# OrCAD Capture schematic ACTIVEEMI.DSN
size Custom
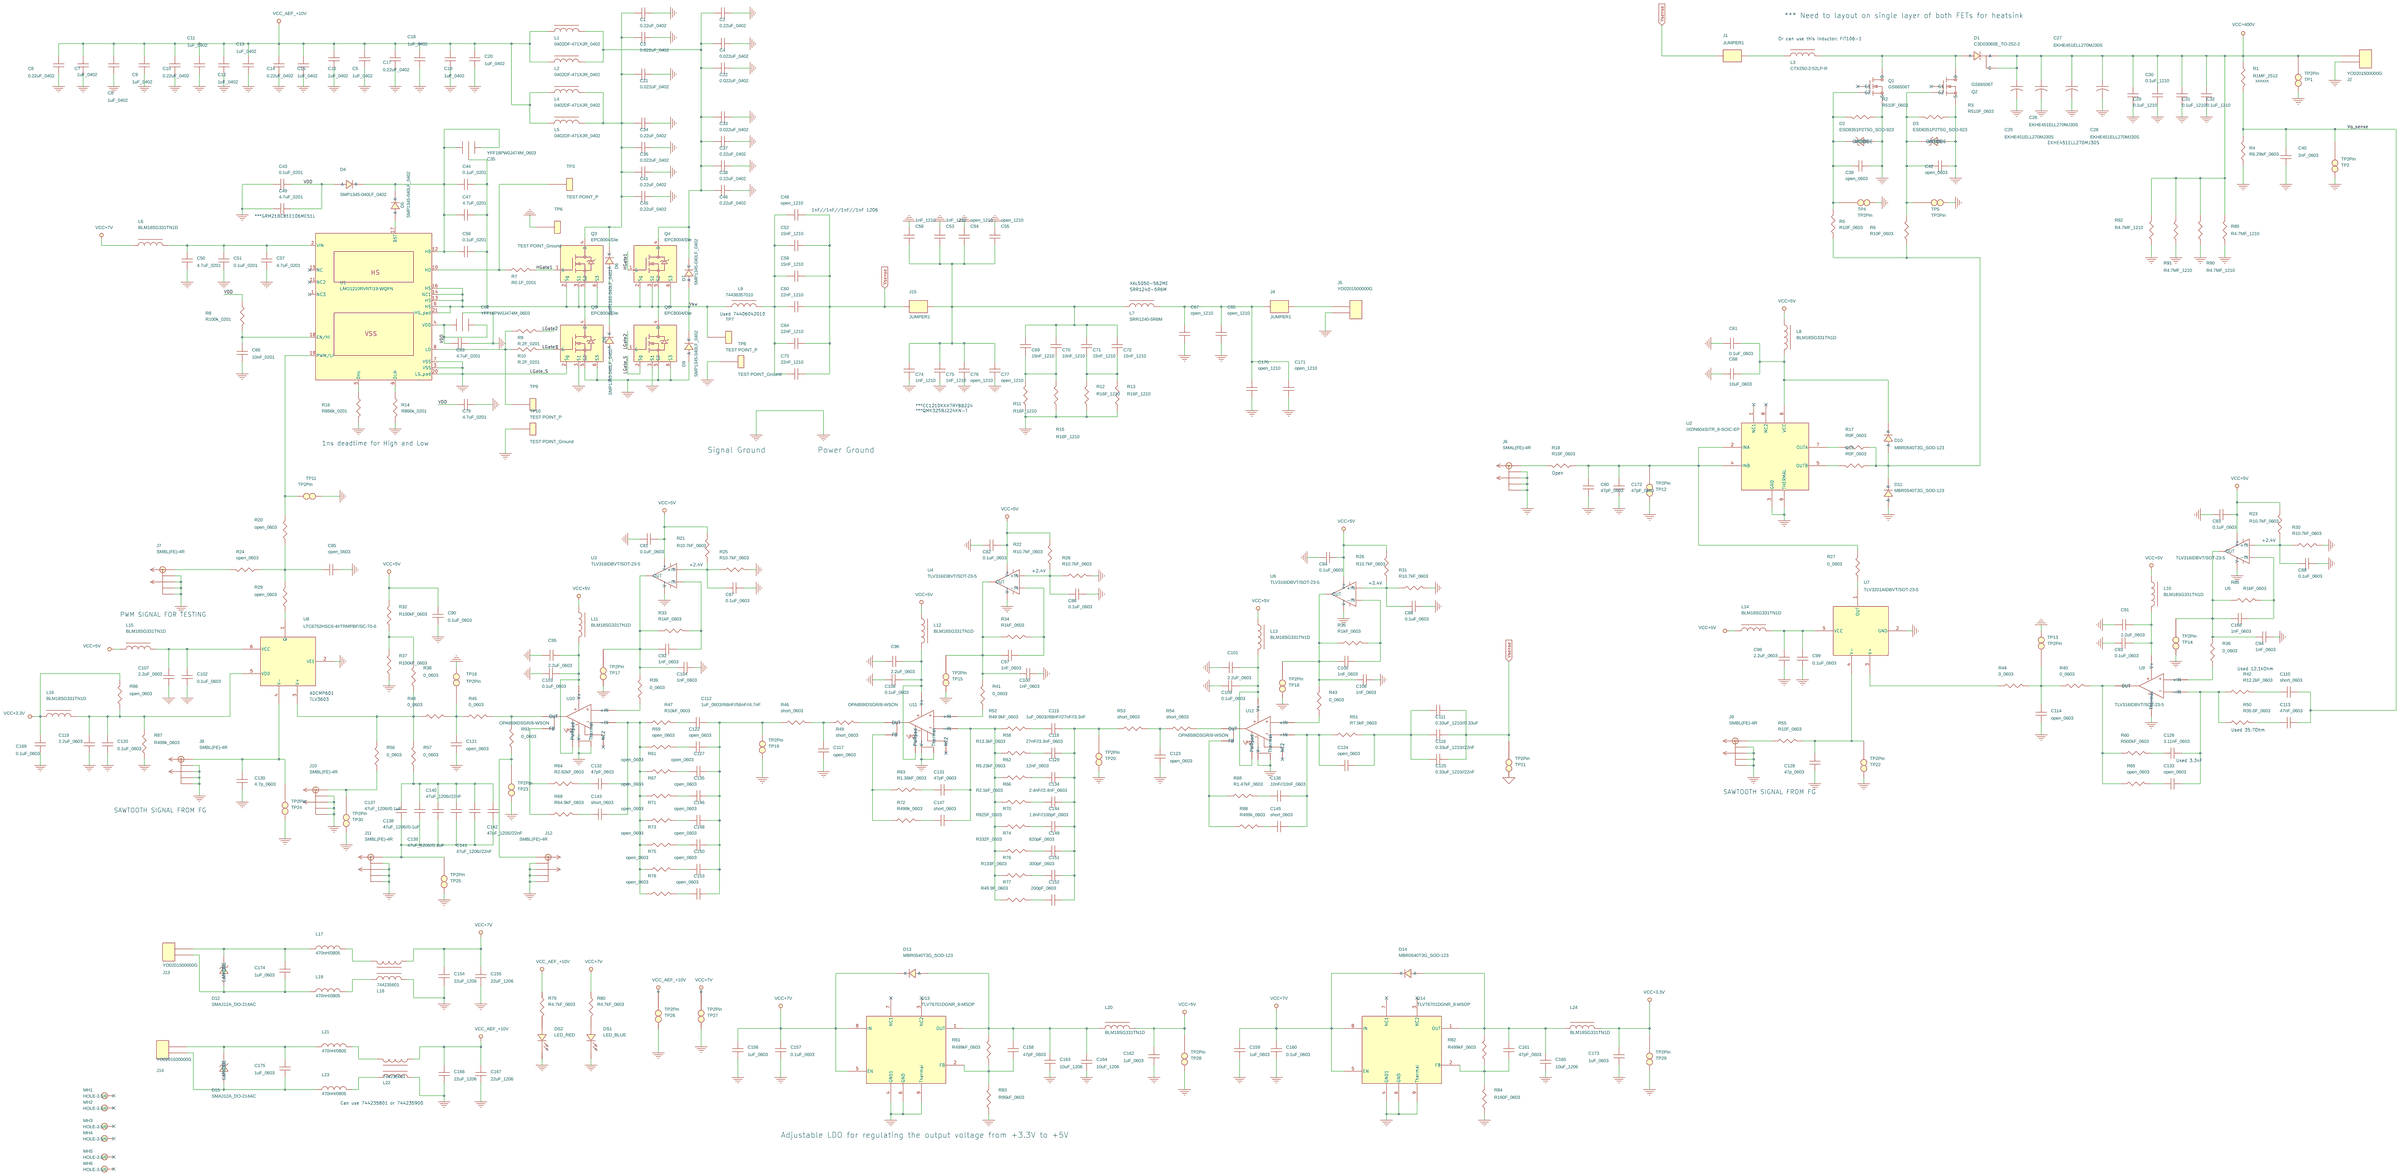
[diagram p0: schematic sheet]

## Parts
C1  0.22uF_0402  [C_0402_SMALL]
C2  0.22uF_0402  [C_0402_SMALL]
C3  0.022uF_0402  [C_0402_SMALL]
C4  0.022uF_0402  [C_0402_SMALL]
C5  1uF_0402  [C_0402_SMALL]
C6  0.22uF_0402  [C_0402_SMALL]
C7  1uF_0402  [C_0402_SMALL]
C8  1uF_0402  [C_0402_SMALL]
C9  1uF_0402  [C_0402_SMALL]
C10  0.22uF_0402  [C_0402_SMALL]
C11  1uF_0402  [C_0402_SMALL]
C12  1uF_0402  [C_0402_SMALL]
C13  1uF_0402  [C_0402_SMALL]
C14  0.22uF_0402  [C_0402_SMALL]
C15  1uF_0402  [C_0402_SMALL]
C16  1uF_0402  [C_0402_SMALL]
C17  0.22uF_0402  [C_0402_SMALL]
C18  1uF_0402  [C_0402_SMALL]
C19  1uF_0402  [C_0402_SMALL]
C20  1uF_0402  [C_0402_SMALL]
C21  0.022uF_0402  [C_0402_SMALL]
C22  0.022uF_0402  [C_0402_SMALL]
C25  EKHE451ELL270MJ30S  [EKHE451ELL270MJ30S]
C26  EKHE451ELL270MJ30S  [EKHE451ELL270MJ30S]
C27  EKHE451ELL270MJ30S  [EKHE451ELL270MJ30S]
C28  EKHE451ELL270MJ30S  [EKHE451ELL270MJ30S]
C29  0.1uF_1210  [22UF_1210]
C30  0.1uF_1210  [22UF_1210]
C31  0.1uF_1210  [22UF_1210]
C32  0.1uF_1210  [22UF_1210]
C33  0.022uF_0402  [C_0402_SMALL]
C34  0.22uF_0402  [C_0402_SMALL]
C35  YFF18PW0J474M_0603  [FEEDTHRU_0603]
C36  0.022uF_0402  [C_0402_SMALL]
C37  0.22uF_0402  [C_0402_SMALL]
C38  0.22uF_0402  [C_0402_SMALL]
C39  open_0603  [C1608]
C40  2nF_0603  [C1608]
C41  0.22uF_0402  [C_0402_SMALL]
C42  open_0603  [C1608]
C43  0.1uF_0201  [C_0201_SHORT]
C44  0.1uF_0201  [C_0201_SHORT]
C45  0.22uF_0402  [C_0402_SMALL]
C46  0.22uF_0402  [C_0402_SMALL]
C47  4.7uF_0201  [C_0201_SHORT]
C48  open_1210  [22UF_1210]
C49  4.7uF_0201  [C_0201_SHORT]
C50  4.7uF_0201  [C_0201_SHORT]
C51  0.1uF_0201  [C_0201_SHORT]
C52  15nF_1210  [22UF_1210]
C53  1nF_1210  [22UF_1210]
C54  open_1210  [22UF_1210]
C55  open_1210  [22UF_1210]
C56  0.1uF_0201  [C_0201_SHORT]
C57  4.7uF_0201  [C_0201_SHORT]
C58  1nF_1210  [22UF_1210]
C59  15nF_1210  [22UF_1210]
C60  22nF_1210  [22UF_1210]
C61  0.1uF_0603  [C1608]
C62  YFF18PW0J474M_0603  [FEEDTHRU_0603]
C63  4.7uF_0201  [C_0201_SHORT]
C64  22nF_1210  [22UF_1210]
C65  open_1210  [22UF_1210]
C66  10nF_0201  [C_0201_SHORT]
C67  open_1210  [22UF_1210]
C68  10uF_0603  [C1608]
C69  15nF_1210  [22UF_1210]
C70  10nF_1210  [22UF_1210]
C71  15nF_1210  [22UF_1210]
C72  15nF_1210  [22UF_1210]
C73  22nF_1210  [22UF_1210]
C74  1nF_1210  [22UF_1210]
C75  1nF_1210  [22UF_1210]
C76  open_1210  [22UF_1210]
C77  open_1210  [22UF_1210]
C79  4.7uF_0201  [C_0201_SHORT]
C80  47pF_0603  [C1608]
C81  0.1uF_0603  [C1608]
C82  0.1uF_0603  [C1608]
C83  0.1uF_0603  [C1608]
C84  0.1uF_0603  [C1608]
C85  open_0603  [C1608]
C86  0.1uF_0603  [C1608]
C87  0.1uF_0603  [C1608]
C88  0.1uF_0603  [C1608]
C89  0.1uF_0603  [C1608]
C90  0.1uF_0603  [C1608]
C91  2.2uF_0603  [C1608]
C92  1nF_0603  [C1608]
C93  0.1uF_0603  [C1608]
C94  1nF_0603  [C1608]
C95  2.2uF_0603  [C1608]
C96  2.2uF_0603  [C1608]
C97  1nF_0603  [C1608]
C98  2.2uF_0603  [C1608]
C99  0.1uF_0603  [C1608]
C100  1nF_0603  [C1608]
C101  2.2uF_0603  [C1608]
C102  0.1uF_0603  [C1608]
C103  0.1uF_0603  [C1608]
C104  1nF_0603  [C1608]
C105  1nF_0603  [C1608]
C106  1nF_0603  [C1608]
C107  2.2uF_0603  [C1608]
C108  0.1uF_0603  [C1608]
C109  0.1uF_0603  [C1608]
C110  short_0603  [C1608]
C111  0.33uF_1210//0.33uF  [22UF_1210]
C112  1uF_0603//68nF//56nF//4.7nF  [C1608]
C113  47nF_0603  [C1608]
C114  open_0603  [C1608]
C115  1uF_0603//68nF//27nF//3.3nF  [C1608]
C116  0.33uF_1210//22nF  [22UF_1210]
C117  open_0603  [C1608]
C118  27nF//3.3nF_0603  [C1608]
C119  2.2uF_0603  [C1608]
C120  0.1uF_0603  [C1608]
C121  open_0603  [C1608]
C122  open_0603  [C1608]
C123  open_0603  [C1608]
C124  open_0603  [C1608]
C125  0.33uF_1210//22nF  [22UF_1210]
C126  3.11nF_0603  [C1608]
C127  open_0603  [C1608]
C128  47p_0603  [C1608]
C129  12nF_0603  [C1608]
C130  4.7p_0603  [C1608]
C131  47pF_0603  [C1608]
C132  47pF_0603  [C1608]
C133  open_0603  [C1608]
C134  2.4nF//2.4nF_0603  [C1608]
C135  open_0603  [C1608]
C136  10nF//10nF_0603  [C1608]
C137  47uF_1206//0.1uF  [OPEN_1206]
C138  47uF_1206//0.1uF  [OPEN_1206]
C139  47uF_1206//0.1uF  [OPEN_1206]
C140  47uF_1206//22nF  [OPEN_1206]
C141  47uF_1206//22nF  [OPEN_1206]
C142  47uF_1206//22nF  [OPEN_1206]
C143  short_0603  [C1608]
C144  1.8nF//100pF_0603  [C1608]
C145  short_0603  [C1608]
C146  open_0603  [C1608]
C147  short_0603  [C1608]
C148  open_0603  [C1608]
C149  820pF_0603  [C1608]
C150  open_0603  [C1608]
C151  300pF_0603  [C1608]
C152  200pF_0603  [C1608]
C153  open_0603  [C1608]
C154  22uF_1206  [OPEN_1206]
C155  22uF_1206  [OPEN_1206]
C156  1uF_0603  [C1608]
C157  0.1uF_0603  [C1608]
C158  47pF_0603  [C1608]
C159  1uF_0603  [C1608]
C160  0.1uF_0603  [C1608]
C161  47pF_0603  [C1608]
C162  1uF_0603  [C1608]
C163  10uF_1206  [OPEN_1206]
C164  10uF_1206  [OPEN_1206]
C165  10uF_1206  [OPEN_1206]
C166  22uF_1206  [OPEN_1206]
C167  22uF_1206  [OPEN_1206]
C168  1nF_0603  [C1608]
C169  0.1uF_0603  [C1608]
C170  open_1210  [22UF_1210]
C171  open_1210  [22UF_1210]
C172  47pF_0603  [C1608]
C173  1uF_0603  [C1608]
C174  1uF_0603  [C1608]
C175  1uF_0603  [C1608]
D1  C3D03065E_TO-252-2  [C3D03065E_TO-252-3]
D2  ESD8351P2T5G_SOD-923  [ESD8351P2T5G]
D3  ESD8351P2T5G_SOD-923  [ESD8351P2T5G]
D4  SMP1345-040LF_0402  [SMP1345-040LF]
D5  SMP1345-040LF_0402  [SMP1345-040LF]
D6  SMP1345-040LF_0402  [SMP1345-040LF]
D7  SMP1345-040LF_0402  [SMP1345-040LF]
D8  SMP1345-040LF_0402  [SMP1345-040LF]
D9  SMP1345-040LF_0402  [SMP1345-040LF]
D10  MBR0540T3G_SOD-123  [MBR0540T3G_SOD-123]
D11  MBR0540T3G_SOD-123  [MBR0540T3G_SOD-123]
D12  SMAJ12A_DO-214AC  [SMAJ6.0CA_DO-214AC]
D13  MBR0540T3G_SOD-123  [MBR0540T3G_SOD-123]
D14  MBR0540T3G_SOD-123  [MBR0540T3G_SOD-123]
D15  SMAJ12A_DO-214AC  [SMAJ6.0CA_DO-214AC]
DS1  LED_BLUE  [598-8170-107F]
DS2  LED_RED  [598-8170-107F]
J1  JUMPER1  [JUMPER3]
J2  YO0201500000G  [YO0201500000G]
J4  JUMPER1  [JUMPER3]
J5  YO0201500000G  [YO0201500000G_INV]
J6  SMAL(FE)-4R  [SMBL(FE)-4R]
J7  SMBL(FE)-4R  [SMBL(FE)-4R]
J8  SMBL(FE)-4R  [SMBL(FE)-4R]
J9  SMBL(FE)-4R  [SMBL(FE)-4R]
J10  SMBL(FE)-4R  [SMBL(FE)-4R]
J11  SMBL(FE)-4R  [SMBL(FE)-4R]
J12  SMBL(FE)-4R  [SMBL(FE)-4R]
J13  YO0201500000G  [YO0201500000G]
J14  YO0201500000G  [YO0201500000G]
J15  JUMPER1  [JUMPER3]
L1  0402DF-471XJR_0402  [L_0402_SMALL]
L2  0402DF-471XJR_0402  [L_0402_SMALL]
L3  CTX250-2-52LP-R  [CTX250-2-52LP-R]
L4  0402DF-471XJR_0402  [L_0402_SMALL]
L5  0402DF-471XJR_0402  [L_0402_SMALL]
L6  BLM18SG331TN1D  [L1608]
L7  SRR1240-5R6M  [SRR1240-5R6M]
L8  BLM18SG331TN1D  [L1608]
L9  74438357010  [74438357010]
L10  BLM18SG331TN1D  [L1608]
L11  BLM18SG331TN1D  [L1608]
L12  BLM18SG331TN1D  [L1608]
L13  BLM18SG331TN1D  [L1608]
L14  BLM18SG331TN1D  [L1608]
L15  BLM18SG331TN1D  [L1608]
L16  BLM18SG331TN1D  [L1608]
L17  470nH/0805  [SM/L_0805]
L18  744235601  [744235601]
L19  470nH/0805  [SM/L_0805]
L20  BLM18SG331TN1D  [L1608]
L21  470nH/0805  [SM/L_0805]
L22  744235601  [744235601]
L23  470nH/0805  [SM/L_0805]
L24  BLM18SG331TN1D  [L1608]
MH1  HOLE-3.5/6  [HOLE-3.2/6]
MH2  HOLE-3.5/6  [HOLE-3.2/6]
MH3  HOLE-3.5/6  [HOLE-3.2/6]
MH4  HOLE-3.5/6  [HOLE-3.2/6]
MH5  HOLE-3.5/6  [HOLE-3.2/6]
MH6  HOLE-3.5/6  [HOLE-3.2/6]
Q1  GS66506T  [GS66506T_SILK]
Q2  GS66506T  [GS66506T_SILK]
Q3  EPC8004/Die  [EPC8004/DIE_SILK]
Q4  EPC8004/Die  [EPC8004/DIE_SILK]
Q5  EPC8004/Die  [EPC8004/DIE_SILK]
Q6  EPC8004/Die  [EPC8004/DIE_SILK]
R1  R1MF_2512  [R_2512]
R2  R510F_0603  [R_1608]
R3  R510F_0603  [R_1608]
R4  R6.29kF_0603  [R_1608]
R5  R10F_0603  [R_1608]
R6  R10F_0603  [R_1608]
R7  R0.1F_0201  [R_0201_SHORT]
R8  R100k_0201  [R_0201_SHORT]
R9  R.2F_0201  [R_0201_SHORT]
R10  R.2F_0201  [R_0201_SHORT]
R11  R16F_1210  [1R0_1210]
R12  R16F_1210  [1R0_1210]
R13  R16F_1210  [1R0_1210]
R14  R866k_0201  [R_0201_SHORT]
R15  R16F_1210  [1R0_1210]
R16  R866k_0201  [R_0201_SHORT]
R17  R0F_0603  [R_1608]
R18  R10F_0603  [R_1608]
R19  R0F_0603  [R_1608]
R20  open_0603  [R_1608]
R21  R10.7kF_0603  [R_1608]
R22  R10.7kF_0603  [R_1608]
R23  R10.7kF_0603  [R_1608]
R24  open_0603  [R_1608]
R25  R10.7kF_0603  [R_1608]
R26  R10.7kF_0603  [R_1608]
R27  0_0603  [R_1608]
R28  R10.7kF_0603  [R_1608]
R29  open_0603  [R_1608]
R30  R10.7kF_0603  [R_1608]
R31  R10.7kF_0603  [R_1608]
R32  R100kF_0603  [R_1608]
R33  R1kF_0603  [R_1608]
R34  R1kF_0603  [R_1608]
R35  R1kF_0603  [R_1608]
R36  0_0603  [R_1608]
R37  R100kF_0603  [R_1608]
R38  0_0603  [R_1608]
R39  0_0603  [R_1608]
R40  0_0603  [R_1608]
R41  0_0603  [R_1608]
R42  R12.2kF_0603  [R_1608]
R43  0_0603  [R_1608]
R44  0_0603  [R_1608]
R45  0_0603  [R_1608]
R46  short_0603  [R_1608]
R47  R10kF_0603  [R_1608]
R48  0_0603  [R_1608]
R49  short_0603  [R_1608]
R50  R35.6F_0603  [R_1608]
R51  R7.5kF_0603  [R_1608]
R52  R49.9kF_0603  [R_1608]
R53  short_0603  [R_1608]
R54  short_0603  [R_1608]
R55  R10F_0603  [R_1608]
R56  0_0603  [R_1608]
R57  0_0603  [R_1608]
R58  R13.3kF_0603  [R_1608]
R59  open_0603  [R_1608]
R60  R500kF_0603  [R_1608]
R61  open_0603  [R_1608]
R62  R5.23kF_0603  [R_1608]
R63  R1.36kF_0603  [R_1608]
R64  R2.82kF_0603  [R_1608]
R65  open_0603  [R_1608]
R66  R2.1kF_0603  [R_1608]
R67  open_0603  [R_1608]
R68  R1.47kF_0603  [R_1608]
R69  R64.9kF_0603  [R_1608]
R70  R825F_0603  [R_1608]
R71  open_0603  [R_1608]
R72  R499k_0603  [R_1608]
R73  open_0603  [R_1608]
R74  R332F_0603  [R_1608]
R75  open_0603  [R_1608]
R76  R133F_0603  [R_1608]
R77  R49.9F_0603  [R_1608]
R78  open_0603  [R_1608]
R79  R4.7kF_0603  [R_1608]
R80  R4.7kF_0603  [R_1608]
R81  R499kF_0603  [R_1608]
R82  R499kF_0603  [R_1608]
R83  R95kF_0603  [R_1608]
R84  R160F_0603  [R_1608]
R85  R1kF_0603  [R_1608]
R86  open_0603  [R_1608]
R87  R499k_0603  [R_1608]
R88  R499k_0603  [R_1608]
R89  R4.7MF_1210  [1R0_1210]
R90  R4.7MF_1210  [1R0_1210]
R91  R4.7MF_1210  [1R0_1210]
R92  R4.7MF_1210  [1R0_1210]
R93  0_0603  [R_1608]
TP1  TP2Pin  [TP2PIN]
TP2  TP2Pin  [TP2PIN]
TP3  TEST POINT_P  [TP1PIN_POS]
TP4  TP2Pin  [TP2PIN]
TP5  TP2Pin  [TP2PIN]
TP6  TEST POINT_Ground  [TP1PIN_NEG]
TP7  TEST POINT_P  [TP1PIN_POS]
TP8  TEST POINT_Ground  [TP1PIN_POS]
TP9  TEST POINT_P  [TP1PIN_POS]
TP10  TEST POINT_Ground  [TP1PIN_NEG]
TP11  TP2Pin  [TP2PIN]
TP12  TP2Pin  [TP2PIN]
TP13  TP2Pin  [TP2PIN]
TP14  TP2Pin  [TP2PIN]
TP15  TP2Pin  [TP2PIN]
TP16  TP2Pin  [TP2PIN]
TP17  TP2Pin  [TP2PIN]
TP18  TP2Pin  [TP2PIN]
TP19  TP2Pin  [TP2PIN]
TP20  TP2Pin  [TP2PIN]
TP21  TP2Pin  [TP2PIN]
TP22  TP2Pin  [TP2PIN]
TP23  TP2Pin  [TP2PIN]
TP24  TP2Pin  [TP2PIN]
TP25  TP2Pin  [TP2PIN]
TP26  TP2Pin  [TP2PIN]
TP27  TP2Pin  [TP2PIN]
TP28  TP2Pin  [TP2PIN]
TP29  TP2Pin  [TP2PIN]
TP30  TP2Pin  [TP2PIN]
U1  LMG1210RVRT/19-WQFN  [LMG1210RVRT_SILK]
U2  IXDN604SITR_8-SOIC-EP  [IXDN604SITR_8-SOIC-EP]
U3  TLV316IDBVT/SOT-23-5  [SN74LVC1G14DBVR_SOT-23-5]
U4  TLV316IDBVT/SOT-23-5  [SN74LVC1G14DBVR_SOT-23-5]
U5  TLV316IDBVT/SOT-23-5  [SN74LVC1G14DBVR_SOT-23-5]
U6  TLV316IDBVT/SOT-23-5  [SN74LVC1G14DBVR_SOT-23-5]
U7  TLV3201AIDBVT/SOT-23-5  [SN74LVC1G14DBVR_SOT-23-5]
U8  LTC6752HSC6-4#TRMPBF/SC-70-6  [SOT-363_LONGER]
U9  TLV316IDBVT/SOT-23-5  [SN74LVC1G14DBVR_SOT-23-5]
U10  OPA859IDSGR/8-WSON  [DJN_IC_9-WSON]
U11  OPA859IDSGR/8-WSON  [DJN_IC_9-WSON]
U12  OPA859IDSGR/8-WSON  [DJN_IC_9-WSON]
U13  TLV76701DGNR_8-MSOP  [TLV76701DGNR_8-MSOP]
U14  TLV76701DGNR_8-MSOP  [TLV76701DGNR_8-MSOP]

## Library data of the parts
C1-C22 C29-C34 C36-C61 C63-C77 C79-C136 C143-C153 C156-C162 C168-C175 = CAP_NP_1
C25-C28 = CAP_0
C35 C62 = CAP_NP_0
C137-C142 = CAP_NP_1: PART NO: 40000677
C154 C155 C163-C167 = CAP_NP_1: PART NO: 151273
D1 = DIODE_2
D2 D3 = DIODE_ZENER_0: PART NO: 40002129
D4-D9 = DIODE_1
D10 D11 D13 D14 = DIODE_5: PART NO: 40001919
D12 D15 = DIODE_ZENER_0
DS1 DS2 = LED_0
J1 J4 J15 = CON2_1
J2 J5 J13 J14 = CON2
J6-J12 = 142-0701-506_0
L1-L5 L7 L9 = INDUCTOR_4
L6 L8 L10-L16 L20 L24 = CHOKE_1_v2
L17 L19 L21 L23 = INDUCTOR
L18 = CHOKE_3
L22 = CHOKE_4
MH1-MH6 = T_POINT_R
Q1 Q2 = IRFZ24N_TO_5: PART NO: 1063683; PATH NO: 1063683
Q3-Q6 = IRFZ24N_TO_2: PATH NO: 1063683
R1 = RESISTOR_0: PART NO: xxxxxx
R2-R10 R14 R16-R78 R81-R88 R93 = R_0
R11-R13 R15 R89-R92 = RESISTOR_0: PART NO: 40000659
R79 R80 = RESISTOR
TP1 TP2 TP4 TP5 TP11-TP30 = T_POINT_R_1
TP3 TP6-TP10 = TEST_POINT
U1 = CON20A_5
U2 = CON8A_9: PART NO: 40000650
U3-U6 = OPA131_SO_0
U7 = CON8A_7
U8 = CON8A_8
U9 = OPA658_SOT_3
U10-U12 = OPA658_SOT_1
U13 U14 = CON8A_6

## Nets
GND_POWER: C1.1 C2.1 C3.1 C4.1 C5.1 C6.1 C7.1 C8.1 C9.1 C10.1 C11.1 C12.1 C13.1 C14.1 C15.1 C16.1 C17.1 C18.1 C19.1 C20.1 C21.1 C22.1 C25.2 C26.2 C27.2 C28.2 C29.2 C30.2 C31.2 C32.2 C33.1 C34.1 C36.1 C37.1 C38.1 C39.2 C40.1 C41.1 C42.2 C43.2 C45.1 C46.1 C49.2 C50.2 C51.2 C53.2 C54.2 C55.2 C57.2 C58.2 C61.1 C62.3 C63.1 C65.2 C66.1 C67.2 C68.1 C74.2 C75.2 C76.2 C77.2 C79.1 C80.1 C81.1 C82.1 C83.1 C84.1 C85.1 C86.2 C87.2 C88.2 C89.2 C90.1 C91.2 C93.1 C94.2 C95.2 C96.2 C98.1 C99.1 C100.2 C101.2 C102.1 C103.1 C104.2 C106.2 C107.1 C108.1 C109.1 C114.1 C117.1 C119.1 C120.1 C121.1 C123.1 C128.1 C130.1 C154.2 C155.2 C156.1 C157.1 C159.1 C160.1 C162.1 C163.2 C164.2 C165.2 C166.2 C167.2 C169.1 C170.2 C171.2 C172.1 C173.1 D2.1(ANODE) D3.1(ANODE) D6.1(A) D9.1(A) D11.1(A) DS1.1(CATHODE) DS2.1(CATHODE) J2.1 J5.2 J6.2 J6.3 J6.4 J6.5 J7.2 J7.3 J7.4 J7.5 J8.2 J8.3 J8.4 J8.5 J9.2 J9.3 J9.4 J9.5 J10.2 J10.3 J10.4 J10.5 J11.2 J11.3 J11.4 J11.5 J12.2 J12.3 J12.4 J12.5 L18.3 L22.3 Q1.3(S) Q2.3(S) Q5.2(Sg) Q5.3(S1) Q5.5(S2) Q5.6(S3) Q6.2(Sg) Q6.3(S1) Q6.5(S2) Q6.6(S3) R2.2 R3.2 R4.2 R11.1 R12.1 R13.1 R14.1 R15.1 R16.1 R25.1 R28.1 R30.1 R31.1 R37.2 R83.2 R84.2 R87.2 R89.1 R90.1 R91.1 R92.1 TP1.2(GND) TP2.2(GND) TP4.2(GND) TP5.2(GND) TP6.1 TP8.1 TP10.1 TP11.2(GND) TP12.2(GND) TP13.2(GND) TP14.2(GND) TP15.2(GND) TP16.2(GND) TP17.2(GND) TP18.2(GND) TP19.2(GND) TP20.2(GND) TP21.2(GND) TP22.2(GND) TP23.2(GND) TP24.2(GND) TP25.2(GND) TP26.2(GND) TP27.2(GND) TP28.2(GND) TP29.2(GND) TP30.2(GND) U1.3(VSS) U1.7(VSS) U1.20(LS_pad) U2.3(GND) U2.9(THERMAL) U3.2(V-) U4.2(V-) U5.2(V-) U6.2(V-) U7.2(GND) U8.2(VEE) U9.2(Thermal) U10.5(V-) U10.9(Thermal) U11.5(V-) U11.9(Thermal) U12.5(V-) U12.9(Thermal) U13.4(GND1) U13.6(GND) U13.9(Thermal) U14.4(GND1) U14.6(GND) U14.9(Thermal)
Vcc+3.3V: C169.2 C173.2 L16.1 L24.2 R86.1 TP29.1(TP)
Vcc+5V: C81.2 C82.2 C83.2 C84.2 C90.2 C162.2 L8.1 L10.1 L11.1 L12.1 L13.1 L14.1 L15.1 L20.2 R21.1 R22.1 R23.1 R26.1 R32.1 TP28.1(TP) U3.5(V+) U4.5(V+) U5.5(V+) U6.5(V+)
Vcc+7V: C154.1 C155.1 C156.2 C157.2 C159.2 C160.2 D13.2(K) D14.2(K) L6.1 L18.2 R80.1 TP27.1(TP) U13.5(EN) U13.8(IN) U14.5(EN) U14.8(IN)
Vcc+400V: C25.1 C26.1 C27.1 C28.1 C29.1 C30.1 C31.1 C32.1 D1.1(A) D1.3(C) J2.2 R1.1 R89.2 R90.2 R91.2 R92.2 TP1.1(TP)
Vcc_AEF_+10V: C5.2 C6.2 C7.2 C8.2 C9.2 C10.2 C11.2 C12.2 C13.2 C14.2 C15.2 C16.2 C17.2 C18.2 C19.2 C20.2 C166.1 C167.1 L1.1 L2.1 L4.1 L5.1 L22.2 R79.1 TP26.1(TP)
VDD: C43.1 C49.1 C62.1 C62.2 C63.2 C79.2 D4.1(A) R8.2 U1.4(VDD)
HGate1: Q3.1(G) Q4.1(G) R7.1
LGate1: Q5.1(G) R10.1
LGate2: Q6.1(G) R9.1
Vo_sense: C40.2 C110.2 C113.2 R1.2 R4.1 TP2.1(TP)
Vsense: C48.1 C52.1 C59.1 C60.1 C64.1 C73.1 C111.2 C116.2 C125.2 J1.1 J15.1 TP21.1(TP)
Vsw: C35.3 C44.1 C47.1 C56.1 D6.2(K) D7.1(A) D8.1(A) D9.2(K) L9.1 Q3.2(Sg) Q3.3(S1) Q3.5(S2) Q3.6(S3) Q4.2(Sg) Q4.3(S1) Q4.5(S2) Q4.6(S3) Q5.4(D) Q6.4(D) TP7.1 U1.9(HS) U1.13(HS) U1.14(NC1) U1.16(HS) U1.21(HS_pad)
N14344006: J7.1 R24.1
N14345447: C1.2 C3.2 C21.2 C34.2 C36.2 C41.2 C45.2 D8.2(K) L4.2 L5.2 Q3.4(D)
N14345453: C2.2 C4.2 C22.2 C33.2 C37.2 C38.2 C46.2 D7.2(K) L1.2 L2.2 Q4.4(D)
N14345780: C48.2 C52.2 C59.2 C60.2 C64.2 C73.2 L9.2
N14346917: C53.1 C54.1 C55.1 C58.1 C69.1 C70.1 C71.1 C72.1 C74.1 C75.1 C76.1 C77.1 J15.2 L7.1
N14346983: C71.2 C72.2 R12.2 R13.2
N14347554: C65.1 C67.1 C170.1 C171.1 J4.1 L7.2
N14354653: C124.1 C136.2 C145.2 R51.2 U12.3(-IN)
N14354665: C111.1 C116.1 C124.2 C125.1 R51.1
N14355323: C136.1 R68.1
N14355343: R68.2 R88.2 U12.1(FB)
N14355725: C101.1 C109.2 L13.2 U12.7(V+) U12.8(PWRpad)
N14356817: C105.1 C106.1 R35.2 R43.1 TP18.1(TP) U6.1(OUT)
N14357001: C105.2 R35.1 U6.4(-IN)
N14357408: C89.1 R26.2 R31.2 U6.3(+IN)
N14359999: C86.1 R22.2 R28.2 U4.3(+IN)
N14360059: C97.1 C100.1 R34.2 R41.1 TP15.1(TP) U4.1(OUT)
N14360067: C97.2 R34.1 U4.4(-IN)
N14360113: C96.1 C108.2 L12.2 U11.7(V+) U11.8(PWRpad)
N14360199: R41.2 U11.4(+IN)
N14360277: R49.1 U11.6(OUT)
N14360317: C131.2 C147.2 R52.1 R58.1 R62.1 R66.1 R70.1 R74.1 R76.1 R77.1 U11.3(-IN)
N14360333: C115.1 C118.1 C129.1 C134.1 C144.1 C149.1 C151.1 C152.1 R53.2 TP20.1(TP)
N14360383: C118.2 R58.2
N14360435: R63.2 R72.2 U11.1(FB)
N14360443: C131.1 R63.1
N14361433: C129.2 R62.2
N14361580: C134.2 R66.2
N14361733: C144.2 R70.2
N14361896: C149.2 R74.2
N14362063: C151.2 R76.2
N14363997: C87.1 R21.2 R25.2 U3.3(+IN)
N14364057: C92.1 C104.1 R33.2 R39.1 TP17.1(TP) U3.1(OUT)
N14364065: C92.2 R33.1 U3.4(-IN)
N14364111: C95.1 C103.2 L11.2 U10.7(V+) U10.8(PWRpad)
N14364215: R39.2 U10.4(+IN)
N14364289: C121.2 R45.2 R48.1 TP16.1(TP)
N14364297: R45.1 R93.1 U10.6(OUT)
N14364337: C132.2 C143.2 R47.2 R59.2 R61.1 R67.1 R71.1 R73.1 R75.1 R78.1 U10.3(-IN)
N14364357: C112.1 R47.1
N14364491: R64.2 R69.2 U10.1(FB)
N14364499: C132.1 R64.1
N14364777: C112.2 C122.2 C127.1 C135.1 C146.1 C148.1 C150.1 C153.1 R46.2 TP19.1(TP)
N14365632: R38.2 R48.2 R56.1 R57.1 U8.3(V+)
N14367350: C130.2 J8.1 TP24.1(TP) U8.4(V-)
N14371364: C102.2 C107.2 L15.2 U8.6(VCC)
N14372288: R29.2 U8.1(Q)
N14372493: C85.2 R20.2 R24.2 R29.1
N14376814: R16.2 U1.5(DHL)
N14376818: R14.2 U1.6(DLH)
N14377829: R20.1 TP11.1(TP) U1.19(PWM/LI)
N14377848: R9.2 R10.2 TP9.1 U1.8(LO)
N14377884: R7.2 TP3.1 U1.10(HO)
N14378663: C35.1 C35.2 C44.2 C47.2 C56.2 D4.2(K) D5.2(K) U1.12(HB)
N14384475: C50.1 C51.1 C57.1 L6.2 U1.2(VIN)
N14385796: C66.2 R8.1 U1.18(EN/HI)
N14445256: R54.1 U12.6(OUT)
N14549198: C69.2 C70.2 R11.2 R15.2
N14555005: D5.1(A) U1.17(BST)
N14663437: J10.1 R56.2 TP30.1(TP)
N14663939: J12.1 R93.2 TP23.1(TP)
N14670381: C137.2 C138.2 C139.2 C140.2 C141.2 C142.2 J11.1 TP25.1(TP)
N14671227: R32.2 R37.1 R38.1
N14672368: C137.1 C138.1 C139.1 C140.1 C141.1 C142.1 R57.2
N14984314: J1.2 L3.1
N14984318: D1.2(K) L3.2 Q1.1(D) Q2.1(D)
N14984604: C39.1 D2.2(CATHODE) Q1.4(G2) R2.1 R5.1 TP4.1(TP)
N14984754: C42.1 D3.2(CATHODE) Q2.4(G2) R3.1 R6.1 TP5.1(TP)
N14985496: D10.1(A) D11.2(K) R5.2 R6.2 R17.2 R19.2
N14986104: C61.2 C68.2 D10.2(K) L8.2 U2.6(VCC)
N14986300: J6.1 R18.1
N14986308: C80.2 C172.2 R18.2 R27.1 TP12.1(TP) U2.2(INA) U2.4(INB)
N15044775: C174.2 D12.2(CATHODE) J13.2 L17.1
N15044799: C174.1 D12.1(ANODE) J13.1 L19.1
N15044925: C175.2 D15.2(CATHODE) J14.2 L21.1
N15044949: C175.1 D15.1(ANODE) J14.1 L23.1
N15050534: R43.2 U12.4(+IN)
N15060765: C152.2 R77.2
N15060962: C115.2 R52.2
N15061047: C147.1 R72.1
N15061956: C123.2 R53.1 R54.2
N15062861: C122.1 R59.1
N15062981: C143.1 R69.1
N15067555: C117.2 R46.1 R49.2
N15072530: C127.2 R61.2
N15072586: C135.2 R67.2
N15072642: C146.2 R71.2
N15072698: C148.2 R73.2
N15072754: C150.2 R75.2
N15072806: C153.2 R78.2
N15082070: J4.2 J5.1
N15096202: L17.2 L18.1
N15096209: L18.4 L19.2
N15101746: L21.2 L22.1
N15101792: L22.4 L23.2
N15112885: C88.1 R23.2 R30.2 U5.3(+IN)
N15112945: C94.1 C168.1 R36.1 R85.2 TP14.1(TP) U5.1(OUT)
N15112953: C168.2 R85.1 U5.4(-IN)
N15112999: C91.1 C93.2 L10.2 U9.5(V+)
N15113221: R36.2 U9.3(+IN)
N15113263: R40.1 R60.2 R65.2 U9.1(OUT)
N15113315: C126.2 C133.2 R42.2 R50.2 U9.4(-IN)
N15113495: C126.1 R60.1
N15114127: C133.1 R65.1
N15114162: C110.1 R42.1
N15114229: C113.1 R50.1
N15116463: R44.2 U7.3(V+)
N15116475: C114.2 R40.2 R44.1 TP13.1(TP)
N15121576: J9.1 R55.2
N15121580: C128.2 R55.1 TP22.1(TP) U7.4(V-)
N15127169: C98.2 C99.2 L14.2 U7.5(VCC)
N15146596: C158.2 C163.1 C164.1 D13.1(A) L20.1 R81.1 U13.1(OUT)
N15151268: C158.1 R81.2 R83.1 U13.2(FB)
N15167322: R27.2 U7.1(OUT)
N15177218: C119.2 C120.2 L16.2 R86.2 R87.1 U8.5(VDD)
N15178335: C161.2 C165.1 D14.1(A) L24.1 R82.1 U14.1(OUT)
N15178577: C161.1 R82.2 R84.1 U14.2(FB)
N15204829: R19.1 U2.5(OUTB)
N15204843: R17.1 U2.7(OUTA)
N15256178: DS1.2(ANODE) R80.2
N15256179: DS2.2(ANODE) R79.2
N15264155: C145.1 R88.1

Not connected (* = marked no-connect by the designer): MH1 1(TP)*; MH2 1(TP)*; MH3 1(TP)*; MH4 1(TP)*; MH5 1(TP)*; MH6 1(TP)*; Q1 2(G1)*; Q2 2(G1)*; U1 1(NC3)* 11(NC2)* 15(NC)*; U2 1(NC1)* 8(NC2)*; U10 2(NC2)*; U11 2(NC2)*; U12 2(NC2)*; U13 3(NC2)* 7(NC1)*; U14 3(NC2)* 7(NC1)*

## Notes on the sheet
- *** Need to layout on single layer of both FETs for heatsink
- Or can use this inductor: FIT106-1
- EKHE451ELL270MJ30S
- 1nF//1nF//1nF//1nF 1206
- ***GRM21BC81E106ME51L
- XAL5050-562ME
- SRR1240-5R6M
- Used 74406042010
- ***CC1210KKX7RYBB224
  ***QMK325BJ224KN-T
- 1ns deadtime for High and Low
- Signal Ground
- Power Ground
- Open
- +2.4V
- +2.4V
- +2.4V
- +2.4V
- PWM SIGNAL FOR TESTING
- Used 12.1kOhm
- ADCMP601
- TLV3603
- Used 35.7Ohm
- Used 3.3nF
- SAWTOOTH SIGNAL FROM FG
- SAWTOOTH SIGNAL FROM FG
- Can use 744235801 or 744235900
- Adjustable LDO for regulating the output voltage from +3.3V to +5V
